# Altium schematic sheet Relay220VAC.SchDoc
size A4; DocumentNumber: 2; SheetNumber: 2; SheetTotal: 4
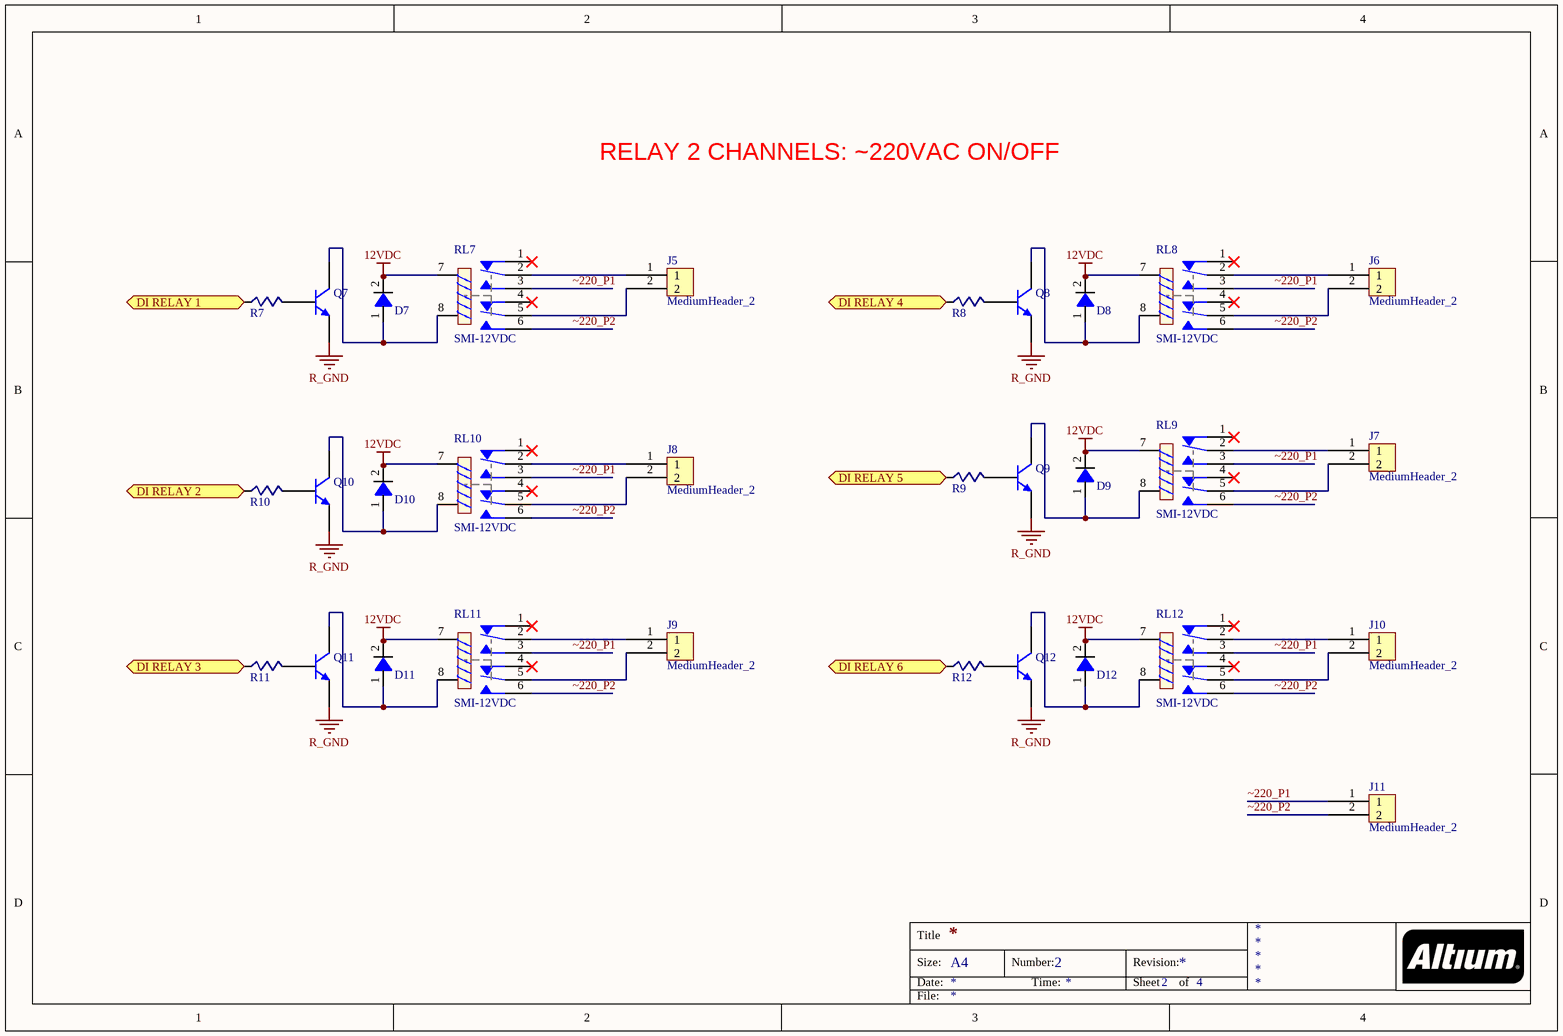
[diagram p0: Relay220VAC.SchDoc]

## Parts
D7  M7 SMD  [Diode 1N4007 SMD]  (value not drawn)
D8  M7 SMD  [Diode 1N4007 SMD]  (value not drawn)
D9  M7 SMD  [Diode 1N4007 SMD]  (value not drawn)
D10  M7 SMD  [Diode 1N4007 SMD]  (value not drawn)
D11  M7 SMD  [Diode 1N4007 SMD]  (value not drawn)
D12  M7 SMD  [Diode 1N4007 SMD]  (value not drawn)
J5  MediumHeader_2  [Medium - Header 2]
J6  MediumHeader_2  [Medium - Header 2]
J7  MediumHeader_2  [Medium - Header 2]
J8  MediumHeader_2  [Medium - Header 2]
J9  MediumHeader_2  [Medium - Header 2]
J10  MediumHeader_2  [Medium - Header 2]
J11  MediumHeader_2  [Medium - Header 2]
Q7  MMBT3904  [SOT23_L_MOD]  (value not drawn)
Q8  MMBT3904  [SOT23_L_MOD]  (value not drawn)
Q9  MMBT3904  [SOT23_L_MOD]  (value not drawn)
Q10  MMBT3904  [SOT23_L_MOD]  (value not drawn)
Q11  MMBT3904  [SOT23_L_MOD]  (value not drawn)
Q12  MMBT3904  [SOT23_L_MOD]  (value not drawn)
R7  R_1K_0603  [RES-SMD-0603]  (value not drawn)
R8  R_1K_0603  [RES-SMD-0603]  (value not drawn)
R9  R_1K_0603  [RES-SMD-0603]  (value not drawn)
R10  R_1K_0603  [RES-SMD-0603]  (value not drawn)
R11  R_1K_0603  [RES-SMD-0603]  (value not drawn)
R12  R_1K_0603  [RES-SMD-0603]  (value not drawn)
RL7  SMI-12VDC  [RELAY SMI-2P]
RL8  SMI-12VDC  [RELAY SMI-2P]
RL9  SMI-12VDC  [RELAY SMI-2P]
RL10  SMI-12VDC  [RELAY SMI-2P]
RL11  SMI-12VDC  [RELAY SMI-2P]
RL12  SMI-12VDC  [RELAY SMI-2P]

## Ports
DI RELAY 1, DI RELAY 2, DI RELAY 3, DI RELAY 4, DI RELAY 5, DI RELAY 6

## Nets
12VDC: D7.2 D8.2 D9.2 D10.2 D11.2 D12.2 RL7.7 RL8.7 RL9.7 RL10.7 RL11.7 RL12.7
R_GND: Q7.2(E) Q8.2(E) Q9.2(E) Q10.2(E) Q11.2(E) Q12.2(E)
DI RELAY 1: R7.1 ; port DI RELAY 1
DI RELAY 2: R10.1 ; port DI RELAY 2
DI RELAY 3: R11.1 ; port DI RELAY 3
DI RELAY 4: R8.1 ; port DI RELAY 4
DI RELAY 5: R9.1 ; port DI RELAY 5
DI RELAY 6: R12.1 ; port DI RELAY 6
~220_P1: J11.1 RL7.3 RL8.3 RL9.3 RL10.3 RL11.3 RL12.3
~220_P2: J11.2 RL7.6 RL8.6 RL9.6 RL10.6 RL11.6 RL12.6
NetD7_1: D7.1 Q7.3(C) RL7.8
NetD8_1: D8.1 Q8.3(C) RL8.8
NetD9_1: D9.1 Q9.3(C) RL9.8
NetD10_1: D10.1 Q10.3(C) RL10.8
NetD11_1: D11.1 Q11.3(C) RL11.8
NetD12_1: D12.1 Q12.3(C) RL12.8
NetJ5_1: J5.1 RL7.2
NetJ5_2: J5.2 RL7.5
NetJ6_1: J6.1 RL8.2
NetJ6_2: J6.2 RL8.5
NetJ7_1: J7.1 RL9.2
NetJ7_2: J7.2 RL9.5
NetJ8_1: J8.1 RL10.2
NetJ8_2: J8.2 RL10.5
NetJ9_1: J9.1 RL11.2
NetJ9_2: J9.2 RL11.5
NetJ10_1: J10.1 RL12.2
NetJ10_2: J10.2 RL12.5
NetQ7_1: Q7.1(B) R7.2
NetQ8_1: Q8.1(B) R8.2
NetQ9_1: Q9.1(B) R9.2
NetQ10_1: Q10.1(B) R10.2
NetQ11_1: Q11.1(B) R11.2
NetQ12_1: Q12.1(B) R12.2

Not connected (* = marked no-connect by the designer): RL7 1* 4*; RL8 1* 4*; RL9 1* 4*; RL10 1* 4*; RL11 1* 4*; RL12 1* 4*

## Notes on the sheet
- RELAY 2 CHANNELS: |20VAC ON/OFF

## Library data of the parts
D7-D12 = Diode_1N4007: DIODE GEN PURP 1KV 1A DO214AC
Q7-Q12 = MMBT3904: TRANSISTOR GP NPN AMP SOT-23
R7-R12 = RES0603_1K: RES 1K OHM 1/10W 1% 0603 SMD
RL7-RL12 = RELAY SMI-2P: Relay 12VDC, 2 channel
